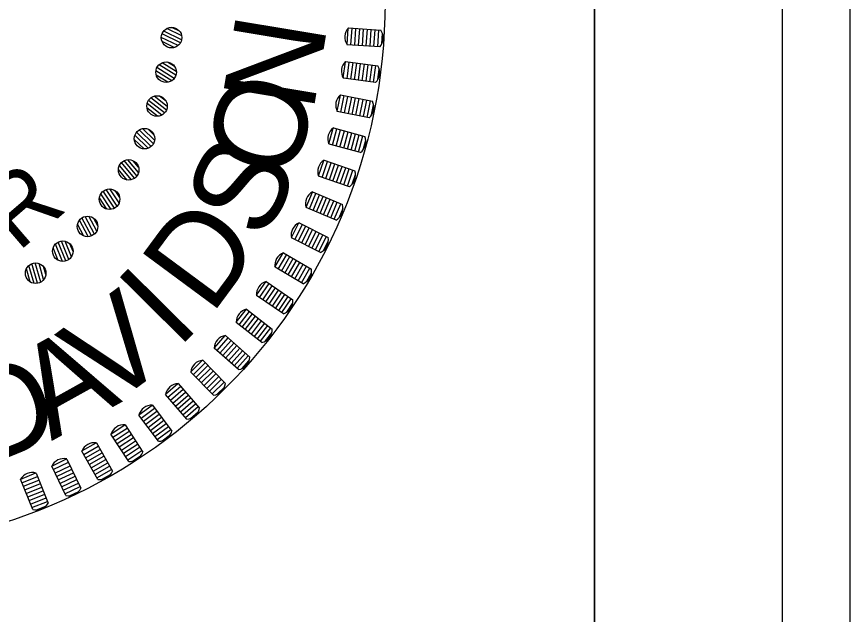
# Model space of a CAD drawing. Extents: x 2111095 to 2115970, y 670428 to 672393.
# Drawn here: x 2113212.2 to 2113267.5, y 672068.3 to 672108 of the extents above; entities that cross this region are included whole.
import ezdxf

# ---------------------------------------------------------------- set-up
doc = ezdxf.new("R2010")
doc.units = 0
for name, color, linetype in [('Sheet PE Seal Cell', 7, 'Continuous'), ('Sheet Plot Border Inside CELL', 7, 'Continuous'), ('Sheet Plot Border Outside CELL', 7, 'Continuous'), ('Sheet Typical CELL', 7, 'Continuous')]:
    doc.layers.add(name, color=color, linetype=linetype)

msp = doc.modelspace()

# ---------------------------------------------------------------- linework, layer by layer
at = {"layer": 'Sheet PE Seal Cell'}
for p, q in [((2113223.025, 672106.211), (2113221.806, 672106.806)), ((2113223.108, 672106.424), (2113221.922, 672107.001)), ((2113223.112, 672106.674), (2113222.117, 672107.159)), ((2113222.961, 672107), (2113222.467, 672107.241)), ((2113234.101, 672106.104), (2113234.173, 672107.19)), ((2113234.185, 672107.203), (2113236.338, 672107.061)), ((2113234.354, 672106.074), (2113234.428, 672107.187)), ((2113234.608, 672106.057), (2113234.682, 672107.171)), ((2113234.863, 672106.04), (2113234.936, 672107.154)), ((2113235.117, 672106.023), (2113235.19, 672107.137)), ((2113235.371, 672106.007), (2113235.444, 672107.12)), ((2113235.625, 672105.99), (2113235.699, 672107.104)), ((2113235.879, 672105.973), (2113235.953, 672107.087)), ((2113236.133, 672105.956), (2113236.207, 672107.07)), ((2113236.402, 672106.157), (2113236.447, 672106.836)), ((2113222.872, 672106.034), (2113221.761, 672106.575)), ((2113222.62, 672105.904), (2113221.813, 672106.297)), ((2113236.265, 672105.948), (2113234.111, 672106.09)), ((2113222.622, 672103.856), (2113221.472, 672104.575)), ((2113222.727, 672104.059), (2113221.608, 672104.757)), ((2113222.757, 672104.307), (2113221.818, 672104.893)), ((2113222.641, 672104.647), (2113222.175, 672104.938)), ((2113233.844, 672103.88), (2113233.987, 672104.959)), ((2113234, 672104.971), (2113236.14, 672104.687)), ((2113234.095, 672103.833), (2113234.242, 672104.939)), ((2113234.347, 672103.799), (2113234.494, 672104.906)), ((2113234.6, 672103.766), (2113234.747, 672104.872)), ((2113234.852, 672103.732), (2113234.999, 672104.839)), ((2113235.105, 672103.698), (2113235.252, 672104.805)), ((2113235.357, 672103.665), (2113235.504, 672104.771)), ((2113235.61, 672103.631), (2113235.757, 672104.738)), ((2113235.862, 672103.598), (2113236.009, 672104.704)), ((2113222.451, 672103.695), (2113221.403, 672104.35)), ((2113222.188, 672103.593), (2113221.426, 672104.068)), ((2113236.143, 672103.781), (2113236.233, 672104.455)), ((2113235.993, 672103.581), (2113233.853, 672103.865)), ((2113221.976, 672101.556), (2113220.907, 672102.391)), ((2113222.1, 672101.746), (2113221.061, 672102.558)), ((2113222.157, 672101.99), (2113221.284, 672102.672)), ((2113222.077, 672102.341), (2113221.644, 672102.679)), ((2113233.441, 672101.677), (2113233.655, 672102.745)), ((2113233.669, 672102.756), (2113235.784, 672102.331)), ((2113233.688, 672101.614), (2113233.907, 672102.708)), ((2113233.937, 672101.563), (2113234.157, 672102.658)), ((2113234.187, 672101.513), (2113234.407, 672102.608)), ((2113234.437, 672101.463), (2113234.657, 672102.558)), ((2113234.686, 672101.413), (2113234.906, 672102.507)), ((2113234.936, 672101.363), (2113235.156, 672102.457)), ((2113235.186, 672101.313), (2113235.406, 672102.407)), ((2113235.436, 672101.263), (2113235.655, 672102.357)), ((2113221.516, 672101.339), (2113220.808, 672101.892)), ((2113221.789, 672101.414), (2113220.814, 672102.175)), ((2113235.728, 672101.426), (2113235.862, 672102.093)), ((2113235.565, 672101.237), (2113233.449, 672101.662)), ((2113221.092, 672099.336), (2113220.116, 672100.278)), ((2113221.236, 672099.512), (2113220.287, 672100.428)), ((2113221.318, 672099.749), (2113220.521, 672100.518)), ((2113221.274, 672100.106), (2113220.879, 672100.487)), ((2113232.892, 672099.506), (2113233.177, 672100.557)), ((2113233.135, 672099.426), (2113233.426, 672100.504)), ((2113233.191, 672100.568), (2113235.274, 672100.004)), ((2113233.381, 672099.36), (2113233.672, 672100.437)), ((2113233.626, 672099.293), (2113233.918, 672100.371)), ((2113233.872, 672099.227), (2113234.164, 672100.304)), ((2113234.118, 672099.16), (2113234.41, 672100.238)), ((2113234.364, 672099.094), (2113234.656, 672100.171)), ((2113234.61, 672099.027), (2113234.902, 672100.105)), ((2113220.612, 672099.169), (2113219.966, 672099.792)), ((2113220.891, 672099.214), (2113220.002, 672100.073)), ((2113234.856, 672098.961), (2113235.147, 672100.038)), ((2113235.159, 672099.105), (2113235.336, 672099.761)), ((2113234.983, 672098.926), (2113232.9, 672099.49)), ((2113220.249, 672097.607), (2113219.537, 672098.455)), ((2113219.769, 672097.12), (2113218.974, 672098.067)), ((2113219.981, 672097.22), (2113219.109, 672098.259)), ((2113220.143, 672097.381), (2113219.295, 672098.39)), ((2113220.243, 672097.967), (2113219.89, 672098.388)), ((2113232.202, 672097.376), (2113232.555, 672098.406)), ((2113232.438, 672097.281), (2113232.801, 672098.336)), ((2113232.57, 672098.415), (2113234.612, 672097.715)), ((2113232.679, 672097.198), (2113233.042, 672098.254)), ((2113232.92, 672097.115), (2113233.282, 672098.171)), ((2113233.161, 672097.033), (2113233.523, 672098.088)), ((2113233.402, 672096.95), (2113233.764, 672098.006)), ((2113233.643, 672096.867), (2113234.005, 672097.923)), ((2113219.486, 672097.104), (2113218.909, 672097.792)), ((2113234.249, 672096.659), (2113232.208, 672097.36)), ((2113233.884, 672096.785), (2113234.246, 672097.841)), ((2113234.125, 672096.702), (2113234.487, 672097.758)), ((2113234.437, 672096.826), (2113234.657, 672097.469)), ((2113218.655, 672095.232), (2113217.897, 672096.357)), ((2113218.833, 672095.375), (2113218.095, 672096.468)), ((2113218.962, 672095.589), (2113218.342, 672096.507)), ((2113218.994, 672095.948), (2113218.686, 672096.403)), ((2113231.372, 672095.297), (2113231.793, 672096.301)), ((2113231.602, 672095.185), (2113232.033, 672096.215)), ((2113231.808, 672096.309), (2113233.799, 672095.475)), ((2113218.151, 672095.169), (2113217.649, 672095.913)), ((2113218.434, 672095.155), (2113217.742, 672096.18)), ((2113231.837, 672095.087), (2113232.268, 672096.117)), ((2113232.072, 672094.989), (2113232.503, 672096.018)), ((2113232.307, 672094.89), (2113232.738, 672095.92)), ((2113232.542, 672094.792), (2113232.973, 672095.821)), ((2113232.777, 672094.693), (2113233.208, 672095.723)), ((2113233.368, 672094.446), (2113231.377, 672095.279)), ((2113233.012, 672094.595), (2113233.443, 672095.625)), ((2113233.247, 672094.497), (2113233.678, 672095.526)), ((2113233.566, 672094.599), (2113233.828, 672095.227)), ((2113217.129, 672093.394), (2113216.492, 672094.591)), ((2113217.32, 672093.517), (2113216.701, 672094.681)), ((2113217.471, 672093.717), (2113216.951, 672094.695)), ((2113217.54, 672094.07), (2113217.282, 672094.555)), ((2113216.62, 672093.383), (2113216.199, 672094.176)), ((2113216.9, 672093.341), (2113216.32, 672094.432)), ((2113230.407, 672093.276), (2113230.893, 672094.25)), ((2113230.629, 672093.15), (2113231.127, 672094.149)), ((2113230.857, 672093.036), (2113231.355, 672094.035)), ((2113230.909, 672094.258), (2113232.84, 672093.294)), ((2113231.085, 672092.923), (2113231.583, 672093.922)), ((2113231.312, 672092.809), (2113231.811, 672093.808)), ((2113231.54, 672092.695), (2113232.039, 672093.694)), ((2113231.768, 672092.582), (2113232.267, 672093.58)), ((2113231.996, 672092.468), (2113232.495, 672093.467)), ((2113215.418, 672091.725), (2113214.91, 672092.983)), ((2113215.622, 672091.828), (2113215.128, 672093.05)), ((2113215.792, 672092.011), (2113215.377, 672093.037)), ((2113232.342, 672092.295), (2113230.411, 672093.259)), ((2113232.224, 672092.354), (2113232.723, 672093.353)), ((2113232.55, 672092.436), (2113232.853, 672093.044)), ((2113214.912, 672091.768), (2113214.575, 672092.6)), ((2113215.186, 672091.696), (2113214.722, 672092.842)), ((2113215.898, 672092.355), (2113215.692, 672092.864)), ((2113229.31, 672091.324), (2113229.859, 672092.264)), ((2113229.523, 672091.184), (2113230.086, 672092.147)), ((2113229.743, 672091.055), (2113230.306, 672092.019)), ((2113229.876, 672092.27), (2113231.739, 672091.181)), ((2113229.963, 672090.926), (2113230.526, 672091.89)), ((2113213.309, 672090.24), (2113212.968, 672091.428)), ((2113213.543, 672090.245), (2113213.169, 672091.548)), ((2113213.756, 672090.325), (2113213.392, 672091.593)), ((2113213.945, 672090.489), (2113213.639, 672091.554)), ((2113214.086, 672090.82), (2113213.935, 672091.348)), ((2113231.176, 672090.218), (2113229.313, 672091.306)), ((2113230.183, 672090.798), (2113230.746, 672091.762)), ((2113230.403, 672090.669), (2113230.966, 672091.633)), ((2113230.623, 672090.541), (2113231.186, 672091.505)), ((2113230.843, 672090.412), (2113231.406, 672091.376)), ((2113231.063, 672090.284), (2113231.626, 672091.248)), ((2113213.044, 672090.34), (2113212.796, 672091.203)), ((2113231.393, 672090.344), (2113231.736, 672090.931)), ((2113228.087, 672089.449), (2113228.697, 672090.35)), ((2113228.29, 672089.294), (2113228.916, 672090.219)), ((2113228.714, 672090.355), (2113230.501, 672089.146)), ((2113228.501, 672089.152), (2113229.127, 672090.076)), ((2113228.712, 672089.009), (2113229.338, 672089.933)), ((2113228.923, 672088.866), (2113229.549, 672089.79)), ((2113229.134, 672088.723), (2113229.759, 672089.648)), ((2113229.876, 672088.221), (2113228.088, 672089.431)), ((2113229.345, 672088.58), (2113229.97, 672089.505)), ((2113229.556, 672088.438), (2113230.181, 672089.362)), ((2113229.767, 672088.295), (2113230.392, 672089.219)), ((2113226.742, 672087.658), (2113227.411, 672088.517)), ((2113227.428, 672088.521), (2113229.131, 672087.196)), ((2113230.1, 672088.333), (2113230.481, 672088.896)), ((2113226.935, 672087.491), (2113227.62, 672088.372)), ((2113227.136, 672087.334), (2113227.821, 672088.215)), ((2113227.337, 672087.178), (2113228.022, 672088.059)), ((2113227.538, 672087.022), (2113228.223, 672087.903)), ((2113228.446, 672086.315), (2113226.742, 672087.64)), ((2113227.739, 672086.865), (2113228.424, 672087.746)), ((2113227.94, 672086.709), (2113228.625, 672087.59)), ((2113228.141, 672086.552), (2113228.826, 672087.433)), ((2113228.342, 672086.396), (2113229.028, 672087.277)), ((2113228.677, 672086.412), (2113229.095, 672086.948)), ((2113225.282, 672085.96), (2113226.006, 672086.774)), ((2113225.463, 672085.781), (2113226.205, 672086.615)), ((2113225.653, 672085.611), (2113226.396, 672086.445)), ((2113225.844, 672085.442), (2113226.586, 672086.276)), ((2113226.023, 672086.777), (2113227.636, 672085.342)), ((2113226.893, 672084.508), (2113225.281, 672085.943)), ((2113226.034, 672085.273), (2113226.776, 672086.107)), ((2113226.224, 672085.103), (2113226.966, 672085.937)), ((2113226.415, 672084.934), (2113227.157, 672085.768)), ((2113226.605, 672084.765), (2113227.347, 672085.599)), ((2113226.795, 672084.595), (2113227.537, 672085.429)), ((2113223.713, 672084.363), (2113224.489, 672085.127)), ((2113223.882, 672084.172), (2113224.678, 672084.955)), ((2113224.061, 672083.99), (2113224.856, 672084.773)), ((2113224.239, 672083.809), (2113225.035, 672084.592)), ((2113224.507, 672085.128), (2113226.02, 672083.59)), ((2113227.13, 672084.589), (2113227.583, 672085.097)), ((2113225.225, 672082.807), (2113223.711, 672084.345)), ((2113224.418, 672083.627), (2113225.214, 672084.41)), ((2113224.597, 672083.446), (2113225.392, 672084.229)), ((2113224.775, 672083.264), (2113225.571, 672084.047)), ((2113222.042, 672082.873), (2113222.867, 672083.583)), ((2113222.884, 672083.584), (2113224.293, 672081.949)), ((2113224.954, 672083.082), (2113225.75, 672083.865)), ((2113225.133, 672082.901), (2113225.928, 672083.684)), ((2113222.198, 672082.671), (2113223.043, 672083.399)), ((2113222.364, 672082.478), (2113223.21, 672083.206)), ((2113222.53, 672082.285), (2113223.376, 672083.013)), ((2113225.467, 672082.872), (2113225.951, 672083.349)), ((2113223.447, 672081.22), (2113222.039, 672082.855)), ((2113222.697, 672082.092), (2113223.542, 672082.821)), ((2113222.863, 672081.899), (2113223.708, 672082.628)), ((2113223.029, 672081.706), (2113223.875, 672082.435)), ((2113220.276, 672081.496), (2113221.146, 672082.151)), ((2113220.418, 672081.284), (2113221.31, 672081.956)), ((2113221.164, 672082.15), (2113222.461, 672080.426)), ((2113223.195, 672081.513), (2113224.041, 672082.242)), ((2113223.362, 672081.32), (2113224.207, 672082.049)), ((2113221.569, 672079.754), (2113220.272, 672081.479)), ((2113220.571, 672081.081), (2113221.463, 672081.752)), ((2113220.724, 672080.877), (2113221.616, 672081.548)), ((2113220.877, 672080.674), (2113221.769, 672081.345)), ((2113223.693, 672081.269), (2113224.208, 672081.713)), ((2113218.423, 672080.239), (2113219.334, 672080.835)), ((2113219.352, 672080.833), (2113220.532, 672079.027)), ((2113221.031, 672080.47), (2113221.923, 672081.141)), ((2113221.184, 672080.267), (2113222.076, 672080.938)), ((2113221.337, 672080.063), (2113222.229, 672080.734)), ((2113219.598, 672078.416), (2113218.417, 672080.222)), ((2113218.551, 672080.019), (2113219.485, 672080.629)), ((2113218.69, 672079.805), (2113219.624, 672080.416)), ((2113218.829, 672079.592), (2113219.764, 672080.203)), ((2113221.49, 672079.86), (2113222.382, 672080.531)), ((2113221.818, 672079.787), (2113222.361, 672080.196)), ((2113216.491, 672079.108), (2113217.439, 672079.642)), ((2113217.457, 672079.639), (2113218.516, 672077.758)), ((2113218.969, 672079.379), (2113219.903, 672079.99)), ((2113219.108, 672079.166), (2113220.042, 672079.776)), ((2113217.543, 672077.211), (2113216.484, 672079.091)), ((2113216.604, 672078.879), (2113217.576, 672079.427)), ((2113216.728, 672078.657), (2113217.701, 672079.205)), ((2113219.247, 672078.952), (2113220.182, 672079.563)), ((2113219.387, 672078.739), (2113220.321, 672079.35)), ((2113219.526, 672078.526), (2113220.461, 672079.137)), ((2113214.488, 672078.106), (2113215.47, 672078.577)), ((2113215.487, 672078.572), (2113216.419, 672076.626)), ((2113216.853, 672078.435), (2113217.826, 672078.983)), ((2113216.978, 672078.213), (2113217.951, 672078.761)), ((2113217.103, 672077.991), (2113218.076, 672078.539)), ((2113219.848, 672078.432), (2113220.417, 672078.804)), ((2113215.412, 672076.144), (2113214.48, 672078.09)), ((2113214.585, 672077.871), (2113215.592, 672078.353)), ((2113214.695, 672077.641), (2113215.702, 672078.123)), ((2113217.228, 672077.769), (2113218.201, 672078.317)), ((2113217.353, 672077.547), (2113218.326, 672078.095)), ((2113212.423, 672077.239), (2113213.434, 672077.644)), ((2113212.505, 672076.998), (2113213.542, 672077.412)), ((2113213.451, 672077.638), (2113214.253, 672075.635)), ((2113214.806, 672077.411), (2113215.812, 672077.893)), ((2113214.916, 672077.181), (2113215.922, 672077.664)), ((2113215.026, 672076.952), (2113216.032, 672077.434)), ((2113217.478, 672077.325), (2113218.451, 672077.873)), ((2113217.793, 672077.21), (2113218.386, 672077.544)), ((2113213.216, 672075.22), (2113212.415, 672077.224)), ((2113212.6, 672076.761), (2113213.636, 672077.176)), ((2113212.694, 672076.525), (2113213.731, 672076.939)), ((2113215.136, 672076.722), (2113216.142, 672077.204)), ((2113215.246, 672076.492), (2113216.252, 672076.974)), ((2113212.789, 672076.288), (2113213.825, 672076.703)), ((2113212.884, 672076.052), (2113213.92, 672076.466)), ((2113215.356, 672076.262), (2113216.362, 672076.745)), ((2113215.662, 672076.127), (2113216.276, 672076.421)), ((2113212.978, 672075.815), (2113214.015, 672076.23)), ((2113213.073, 672075.579), (2113214.109, 672075.993)), ((2113213.167, 672075.342), (2113214.204, 672075.757)), ((2113213.465, 672075.187), (2113214.096, 672075.439))]:
    msp.add_line(p, q, dxfattribs=at)
for centre, radius in [((2113200.402, 672108.877), 36.215), ((2113222.441, 672106.561), 0.681), ((2113222.078, 672104.264), 0.681), ((2113221.477, 672102.019), 0.681), ((2113220.644, 672099.848), 0.681), ((2113219.589, 672097.777), 0.681), ((2113218.324, 672095.827), 0.681), ((2113216.861, 672094.02), 0.681), ((2113215.218, 672092.376), 0.681), ((2113213.412, 672090.912), 0.681)]:
    msp.add_circle(centre, radius, dxfattribs=at)
for centre, radius, start, end in [((2113234.824, 672106.602), 0.878, 136.7281, 215.7216), ((2113235.57, 672106.553), 0.922, 318.9543, 33.4953), ((2113234.598, 672104.329), 0.878, 132.9386, 211.9321), ((2113235.339, 672104.23), 0.922, 315.1649, 29.7058), ((2113234.223, 672102.075), 0.878, 129.1491, 208.1426), ((2113234.955, 672101.928), 0.922, 311.3754, 25.9164), ((2113233.699, 672099.852), 0.878, 125.3596, 204.3531), ((2113234.421, 672099.657), 0.922, 307.5859, 22.1269), ((2113233.03, 672097.668), 0.878, 121.5702, 200.5637), ((2113233.737, 672097.425), 0.922, 303.7964, 18.3374), ((2113232.217, 672095.533), 0.878, 117.7807, 196.7742), ((2113232.907, 672095.244), 0.922, 300.007, 14.5479), ((2113231.266, 672093.456), 0.878, 113.9912, 192.9847), ((2113231.935, 672093.122), 0.922, 296.2175, 10.7585), ((2113230.179, 672091.447), 0.878, 110.2018, 189.1952), ((2113230.824, 672091.069), 0.922, 292.428, 6.969), ((2113228.962, 672089.514), 0.878, 106.4123, 185.4058), ((2113229.581, 672089.095), 0.922, 288.6385, 3.1795), ((2113227.62, 672087.665), 0.878, 102.6228, 181.6163), ((2113228.21, 672087.206), 0.922, 284.8491, 359.39), ((2113226.158, 672085.909), 0.878, 98.8333, 177.8268), ((2113226.717, 672085.412), 0.922, 281.0596, 355.6006), ((2113224.584, 672084.254), 0.878, 95.0439, 174.0374), ((2113222.904, 672082.707), 0.878, 91.2544, 170.2479), ((2113225.108, 672083.721), 0.922, 277.2701, 351.8111), ((2113221.125, 672081.273), 0.878, 87.4649, 166.4584), ((2113223.392, 672082.14), 0.922, 273.4806, 348.0216), ((2113219.255, 672079.961), 0.878, 83.6754, 162.6689), ((2113221.574, 672080.676), 0.922, 269.6912, 344.2321), ((2113217.303, 672078.775), 0.878, 79.886, 158.8795), ((2113215.276, 672077.721), 0.878, 76.0965, 155.09), ((2113219.664, 672079.335), 0.922, 265.9017, 340.4427), ((2113213.184, 672076.802), 0.878, 72.307, 151.3005), ((2113217.669, 672078.124), 0.922, 262.1122, 336.6532), ((2113215.599, 672077.046), 0.922, 258.3228, 332.8637), ((2113213.462, 672076.108), 0.922, 254.5333, 329.0742)]:
    msp.add_arc(centre, radius, start, end, dxfattribs=at)
at = {"layer": 'Sheet Plot Border Inside CELL'}
msp.add_lwpolyline([(2113263.023, 672193.583), (2111596.523, 672193.583), (2111596.523, 671138.483), (2113263.023, 671138.483)], close=True, dxfattribs=at)
at = {"layer": 'Sheet Plot Border Outside CELL'}
msp.add_lwpolyline([(2113267.523, 672216.033), (2111583.523, 672216.033), (2111583.523, 671116.033), (2113267.523, 671116.033)], close=True, dxfattribs=at)
at = {"layer": 'Sheet Typical CELL'}
for points in [[(2113250.523, 672191.033), (2111750.523, 672191.033), (2111750.523, 671141.033), (2113250.523, 671141.033)], [(2113150.523, 672165.983), (2113250.523, 672165.983), (2113250.523, 672053.483), (2113150.523, 672053.483)]]:
    msp.add_lwpolyline(points, close=True, dxfattribs=at)

# ---------------------------------------------------------------- texts
at = {"layer": 'Sheet PE Seal Cell'}
for s, height, rotation, p in [('N', 6.113, 80.563, (2113231.839, 672101.537)), ('O', 6.113, 72.2769, (2113230.322, 672096.864)), ('S', 6.113, 63.5765, (2113228.558, 672092.946)), ('R', 4.585, 40.6595, (2113212.238, 672092.275)), ('D', 6.113, 53.5348, (2113225.07, 672088.052)), ('I', 6.113, 45.2487, (2113222.825, 672085.82)), ('V', 6.113, 36.5483, (2113218.243, 672081.891)), ('A', 6.113, 29.0908, (2113214.462, 672079.753)), ('D', 6.113, 22.0477, (2113209.961, 672078.019))]:
    msp.add_text(s, height=height, rotation=rotation, dxfattribs=at).set_placement(p)

doc.saveas('drawing.dxf')
